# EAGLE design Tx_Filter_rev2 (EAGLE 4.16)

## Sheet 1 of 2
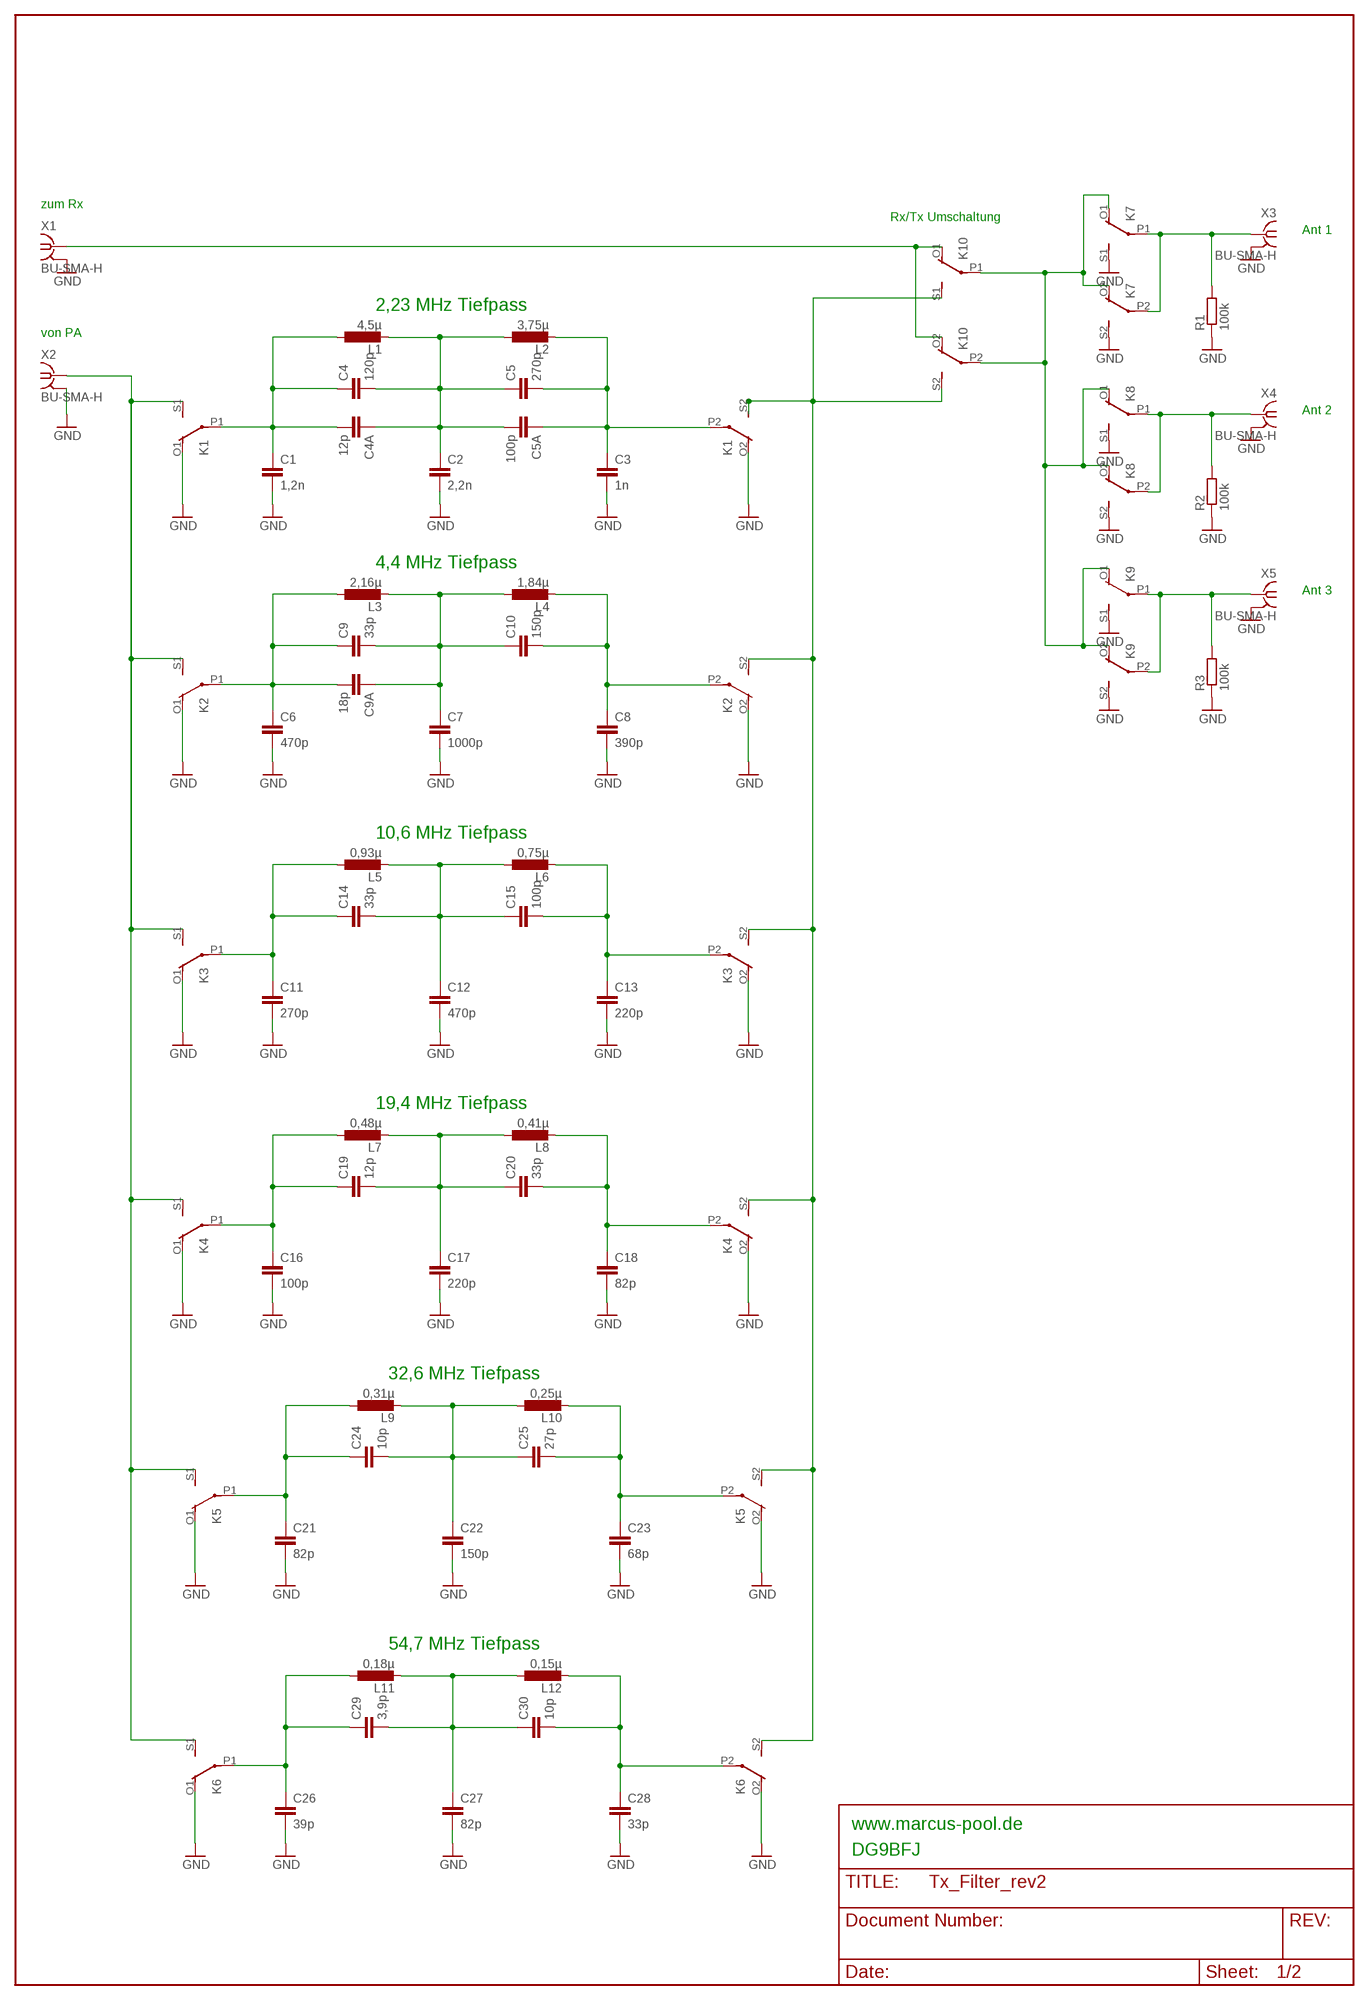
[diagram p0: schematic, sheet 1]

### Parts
C1  1,2n  C-EU050-035X075  [C050-035X075]
C2  2,2n  C-EU050-035X075  [C050-035X075]
C3  1n  C-EU050-035X075  [C050-035X075]
C4  120p  C-EU050-035X075  [C050-035X075]
C4A  12p  C-EU050-035X075  [C050-035X075]
C5  270p  C-EU050-035X075  [C050-035X075]
C5A  100p  C-EU050-035X075  [C050-035X075]
C6  470p  C-EU050-035X075  [C050-035X075]
C7  1000p  C-EU050-035X075  [C050-035X075]
C8  390p  C-EU050-035X075  [C050-035X075]
C9  33p  C-EU050-035X075  [C050-035X075]
C9A  18p  C-EU050-035X075  [C050-035X075]
C10  150p  C-EU050-035X075  [C050-035X075]
C11  270p  C-EU050-035X075  [C050-035X075]
C12  470p  C-EU050-035X075  [C050-035X075]
C13  220p  C-EU050-035X075  [C050-035X075]
C14  33p  C-EU050-035X075  [C050-035X075]
C15  100p  C-EU050-035X075  [C050-035X075]
C16  100p  C-EU050-035X075  [C050-035X075]
C17  220p  C-EU050-035X075  [C050-035X075]
C18  82p  C-EU050-035X075  [C050-035X075]
C19  12p  C-EU050-035X075  [C050-035X075]
C20  33p  C-EU050-035X075  [C050-035X075]
C21  82p  C-EU050-035X075  [C050-035X075]
C22  150p  C-EU050-035X075  [C050-035X075]
C23  68p  C-EU050-035X075  [C050-035X075]
C24  10p  C-EU050-035X075  [C050-035X075]
C25  27p  C-EU050-035X075  [C050-035X075]
C26  39p  C-EU050-035X075  [C050-035X075]
C27  82p  C-EU050-035X075  [C050-035X075]
C28  33p  C-EU050-035X075  [C050-035X075]
C29  3,9p  C-EU050-035X075  [C050-035X075]
C30  10p  C-EU050-035X075  [C050-035X075]
K1  G6H2-100  [G6H2-100]
K2  G6H2-100  [G6H2-100]
K3  G6H2-100  [G6H2-100]
K4  G6H2-100  [G6H2-100]
K5  G6H2-100  [G6H2-100]
K6  G6H2-100  [G6H2-100]
K7  G6H2-100  [G6H2-100]
K8  G6H2-100  [G6H2-100]
K9  G6H2-100  [G6H2-100]
K10  G6H2-100  [G6H2-100]
L1  4,5µ  L-EUTJ3-U1  [TJ3-U1]
L2  3,75µ  L-EUTJ3-U1  [TJ3-U1]
L3  2,16µ  L-EUTJ3-U1  [TJ3-U1]
L4  1,84µ  L-EUTJ3-U1  [TJ3-U1]
L5  0,93µ  L-EUTJ3-U1  [TJ3-U1]
L6  0,75µ  L-EUTJ3-U1  [TJ3-U1]
L7  0,48µ  L-EUTJ3-U1  [TJ3-U1]
L8  0,41µ  L-EUTJ3-U1  [TJ3-U1]
L9  0,31µ  L-EUTJ3-U1  [TJ3-U1]
L10  0,25µ  L-EUTJ3-U1  [TJ3-U1]
L11  0,18µ  L-EUTJ3-U1  [TJ3-U1]
L12  0,15µ  L-EUTJ3-U1  [TJ3-U1]
R1  100k  R-EU_M0805  [M0805]
R2  100k  R-EU_M0805  [M0805]
R3  100k  R-EU_M0805  [M0805]
X1  BU-SMA-H  [BU-SMA-H]
X2  BU-SMA-H  [BU-SMA-H]
X3  BU-SMA-H  [BU-SMA-H]
X4  BU-SMA-H  [BU-SMA-H]
X5  BU-SMA-H  [BU-SMA-H]

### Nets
GND: C1.2 C2.2 C3.2 C6.2 C7.2 C8.2 C11.2 C12.2 C13.2 C16.2 C17.2 C18.2 C21.2 C22.2 C23.2 C26.2 C27.2 C28.2 K1.O1(2:O) K1.O2(3:O) K2.O1(2:O) K2.O2(3:O) K3.O1(2:O) K3.O2(3:O) K4.O1(2:O) K4.O2(3:O) K5.O1(2:O) K5.O2(3:O) K6.O1(2:O) K6.O2(3:O) K7.S1(2:S) K7.S2(3:S) K8.S1(2:S) K8.S2(3:S) K9.S1(2:S) K9.S2(3:S) R1.1 R2.1 R3.1 X1.2(GND) X2.2(GND) X3.2(GND) X4.2(GND) X5.2(GND) ; also sheet 2
N$1: C1.1 C4.1 C4A.2 K1.P1(2:P) L1.1
N$2: C2.1 C4.2 C4A.1 C5.1 C5A.2 L1.2 L2.1
N$3: C6.1 C9.1 C9A.2 K2.P1(2:P) L3.1
N$4: C8.1 C10.2 K2.P2(3:P) L4.2
N$5: C3.1 C5.2 C5A.1 K1.P2(3:P) L2.2
N$6: C7.1 C9.2 C9A.1 C10.1 L3.2 L4.1
N$7: C11.1 C14.1 K3.P1(2:P) L5.1
N$8: C13.1 C15.2 K3.P2(3:P) L6.2
N$9: C12.1 C14.2 C15.1 L5.2 L6.1
N$10: C16.1 C19.1 K4.P1(2:P) L7.1
N$11: C18.1 C20.2 K4.P2(3:P) L8.2
N$12: C17.1 C19.2 C20.1 L7.2 L8.1
N$13: C21.1 C24.1 K5.P1(2:P) L9.1
N$14: C23.1 C25.2 K5.P2(3:P) L10.2
N$15: C22.1 C24.2 C25.1 L9.2 L10.1
N$16: C26.1 C29.1 K6.P1(2:P) L11.1
N$17: C28.1 C30.2 K6.P2(3:P) L12.2
N$18: C27.1 C29.2 C30.1 L11.2 L12.1
N$21: K7.P1(2:P) K7.P2(3:P) R1.2 X3.1
N$22: K7.O1(2:O) K7.O2(3:O) K8.O1(2:O) K8.O2(3:O) K9.O1(2:O) K9.O2(3:O) K10.P1(2:P) K10.P2(3:P)
N$24: K8.P1(2:P) K8.P2(3:P) R2.2 X4.1
N$25: K9.P1(2:P) K9.P2(3:P) R3.2 X5.1
RX: K10.O1(2:O) K10.O2(3:O) X1.1
TX_IN: K1.S1(2:S) K2.S1(2:S) K3.S1(2:S) K4.S1(2:S) K5.S1(2:S) K6.S1(2:S) X2.1
TX_OUT: K1.S2(3:S) K2.S2(3:S) K3.S2(3:S) K4.S2(3:S) K5.S2(3:S) K6.S2(3:S) K10.S1(2:S) K10.S2(3:S)

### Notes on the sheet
- zum Rx
- Rx/Tx Umschaltung
- Ant 1
- 2,23 MHz Tiefpass
- von PA
- Ant 2
- 4,4 MHz Tiefpass
- Ant 3
- 10,6 MHz Tiefpass
- 19,4 MHz Tiefpass
- 32,6 MHz Tiefpass
- 54,7 MHz Tiefpass
- www.marcus-pool.de
- DG9BFJ

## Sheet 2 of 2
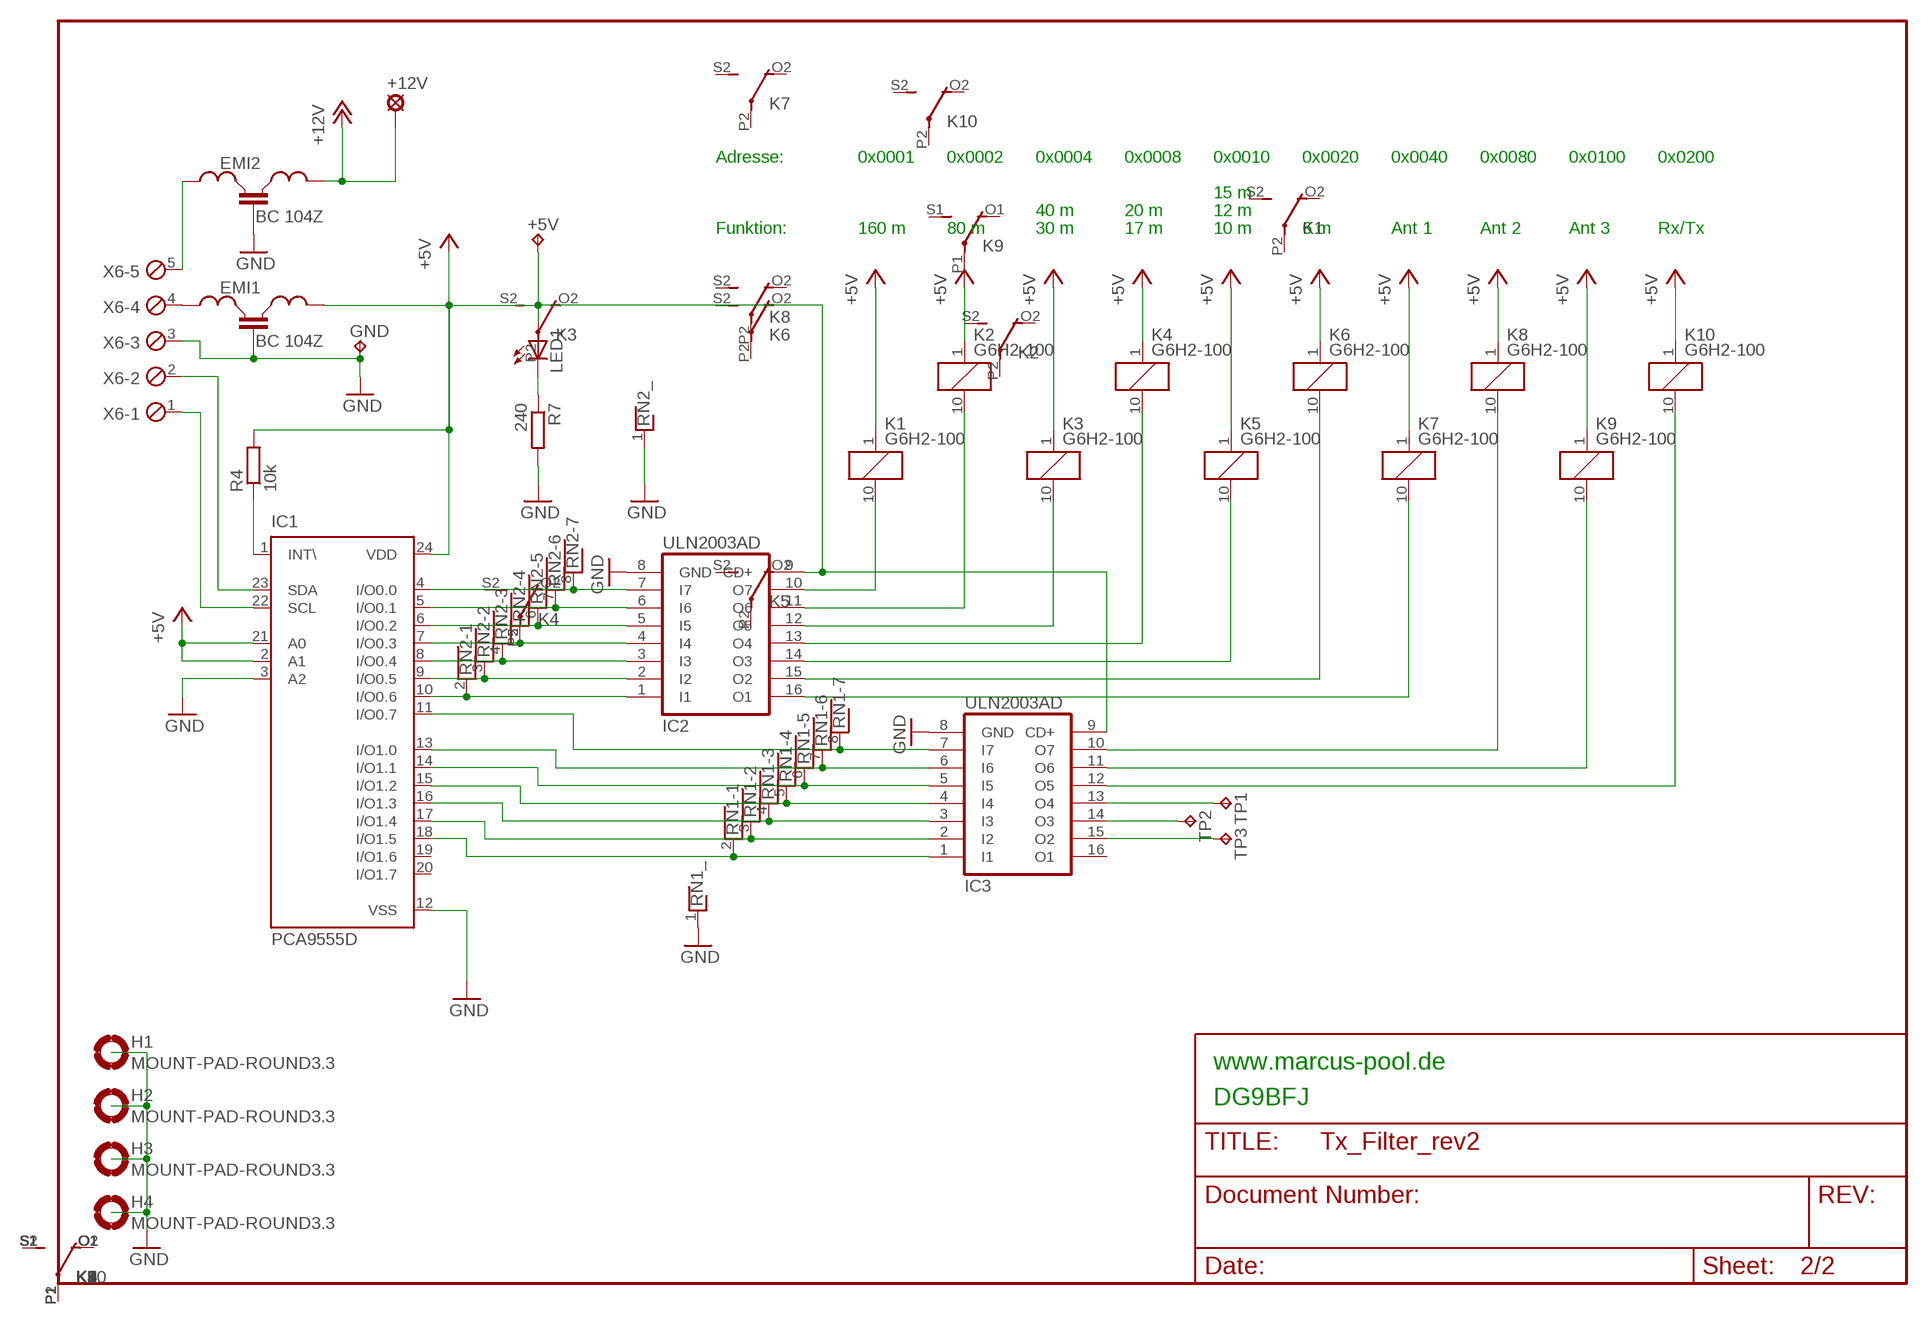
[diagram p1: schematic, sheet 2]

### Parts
+5V  TPB2,54  [B2,54]
+12V  LSP10  [LSP10]
EMI1  BC 104Z  DSS30655  [DSS30655]
EMI2  BC 104Z  DSS30655  [DSS30655]
GND  TPB2,54  [B2,54]
H1  MOUNT-PAD-ROUND3.3  [3,3-PAD]
H2  MOUNT-PAD-ROUND3.3  [3,3-PAD]
H3  MOUNT-PAD-ROUND3.3  [3,3-PAD]
H4  MOUNT-PAD-ROUND3.3  [3,3-PAD]
IC1  PCA9555D  [SO24]
IC2  ULN2003AD  [SO16]
IC3  ULN2003AD  [SO16]
LED1  LEDCHIP-LED0805  [CHIP-LED0805]
R4  10k  R-EU_M0805  [M0805]
R7  240  R-EU_M0805  [M0805]
RN1  RNX7  [RN-8]
RN2  RNX7  [RN-8]
TP1  TPB2,54  [B2,54]
TP2  TPB2,54  [B2,54]
TP3  TPB2,54  [B2,54]
X6  MPT5  [5POL254]

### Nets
+5V: +5V.PP(TP) EMI1.3 IC1.2(A1) IC1.21(A0) IC1.24(VDD) IC2.9(CD+) IC3.9(CD+) K1.1 K2.1 K3.1 K4.1 K5.1 K6.1 K7.1 K8.1 K9.1 K10.1 LED1.A R4.2
+12V: +12V.MP EMI2.3
GND: EMI1.2 EMI2.2 GND.PP(TP) H1.B3,3(MOUNT) H2.B3,3(MOUNT) H3.B3,3(MOUNT) H4.B3,3(MOUNT) IC1.3(A2) IC1.12(VSS) IC2.8(GND) IC3.8(GND) R7.2 RN1.1 RN2.1 X6.3 ; also sheet 1
N$19: IC1.10(I/O0.6) IC2.1(I1) RN2.2
N$20: IC2.10(O7) K1.10
N$23: IC2.11(O6) K2.10
N$26: IC2.12(O5) K3.10
N$27: IC2.13(O4) K4.10
N$28: IC2.14(O3) K5.10
N$29: IC2.15(O2) K6.10
N$30: IC2.16(O1) K7.10
N$31: IC3.10(O7) K8.10
N$32: IC1.11(I/O0.7) IC3.7(I7) RN1.8
N$33: IC1.13(I/O1.0) IC3.6(I6) RN1.7
N$34: IC1.9(I/O0.5) IC2.2(I2) RN2.3
N$35: IC1.14(I/O1.1) IC3.5(I5) RN1.6
N$36: IC1.15(I/O1.2) IC3.4(I4) RN1.5
N$37: IC1.16(I/O1.3) IC3.3(I3) RN1.4
N$38: IC1.17(I/O1.4) IC3.2(I2) RN1.3
N$39: IC1.8(I/O0.4) IC2.3(I3) RN2.4
N$40: IC1.7(I/O0.3) IC2.4(I4) RN2.5
N$41: IC1.6(I/O0.2) IC2.5(I5) RN2.6
N$42: IC1.5(I/O0.1) IC2.6(I6) RN2.7
N$43: IC1.4(I/O0.0) IC2.7(I7) RN2.8
N$44: IC1.18(I/O1.5) IC3.1(I1) RN1.2
N$45: IC3.11(O6) K9.10
N$46: IC3.12(O5) K10.10
N$47: IC1.1(INT\) R4.1
N$48: IC3.15(O2) TP3.PP(TP)
N$49: IC3.14(O3) TP2.PP(TP)
N$50: IC3.13(O4) TP1.PP(TP)
N$51: EMI1.1 X6.4
N$52: EMI2.1 X6.5
N$70: IC1.22(SCL) X6.1
N$71: IC1.23(SDA) X6.2
N$72: LED1.C R7.1
Unconnected: IC1.19(I/O1.6) IC1.20(I/O1.7) IC3.16(O1)

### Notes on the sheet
- Adresse: | 0x0001 | 0x0002 | 0x0004 | 0x0008 | 0x0010 | 0x0020 | 0x0040 | 0x0080 | 0x0100 | 0x0200
- 15 m
- 40 m | 20 m | 12 m
- Funktion: | 160 m | 80 m | 30 m | 17 m | 10 m | 6 m | Ant 1 | Ant 2 | Ant 3 | Rx/Tx
- www.marcus-pool.de
- DG9BFJ

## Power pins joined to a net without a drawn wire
GND: X1.3(GND) X1.4(GND) X1.5(GND) X2.3(GND) X2.4(GND) X2.5(GND) X3.3(GND) X3.4(GND) X3.5(GND) X4.3(GND) X4.4(GND) X4.5(GND) X5.3(GND) X5.4(GND) X5.5(GND)

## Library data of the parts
+5V GND TP1-TP3 = RSC_IB_LIB:TP
+12V = solpad:LSP10: SOLDER PAD
C1-C4 C4A C5 C5A C6-C9 C9A C10-C30 = rcl:C-EU: CAPACITOR, European symbol
EMI1 EMI2 = ds(s)30655:DSS30655
H1-H4 = holes:MOUNT-PAD-ROUND: MOUNTING PAD, round
IC1 = micro-philips:PCA9555: 16-bit I2C and SMBus I/O port with interrupt Source: PCA9555_5.pdf
IC2 IC3 = uln-udn:ULN2003A: DRIVER ARRAY
K1-K10 = relay:G6H2-100: RELAY 2 x switch, 0.5 A/125 V AC, 1 A/30 V DC, Omron
L1-L12 = rcl:L-EU: INDUCTOR, European symbol
LED1 = led:LED: LED
R1-R4 R7 = rcl:R-EU_: RESISTOR, European symbol
RN1 RN2 = resistor-net:RNX7: RESISTOR NETWORK
X1-X5 = RSC_IB_LIB:BU-SMA-H
X6 = con-phoenix-254:MPT5: PHOENIX CONNECTOR

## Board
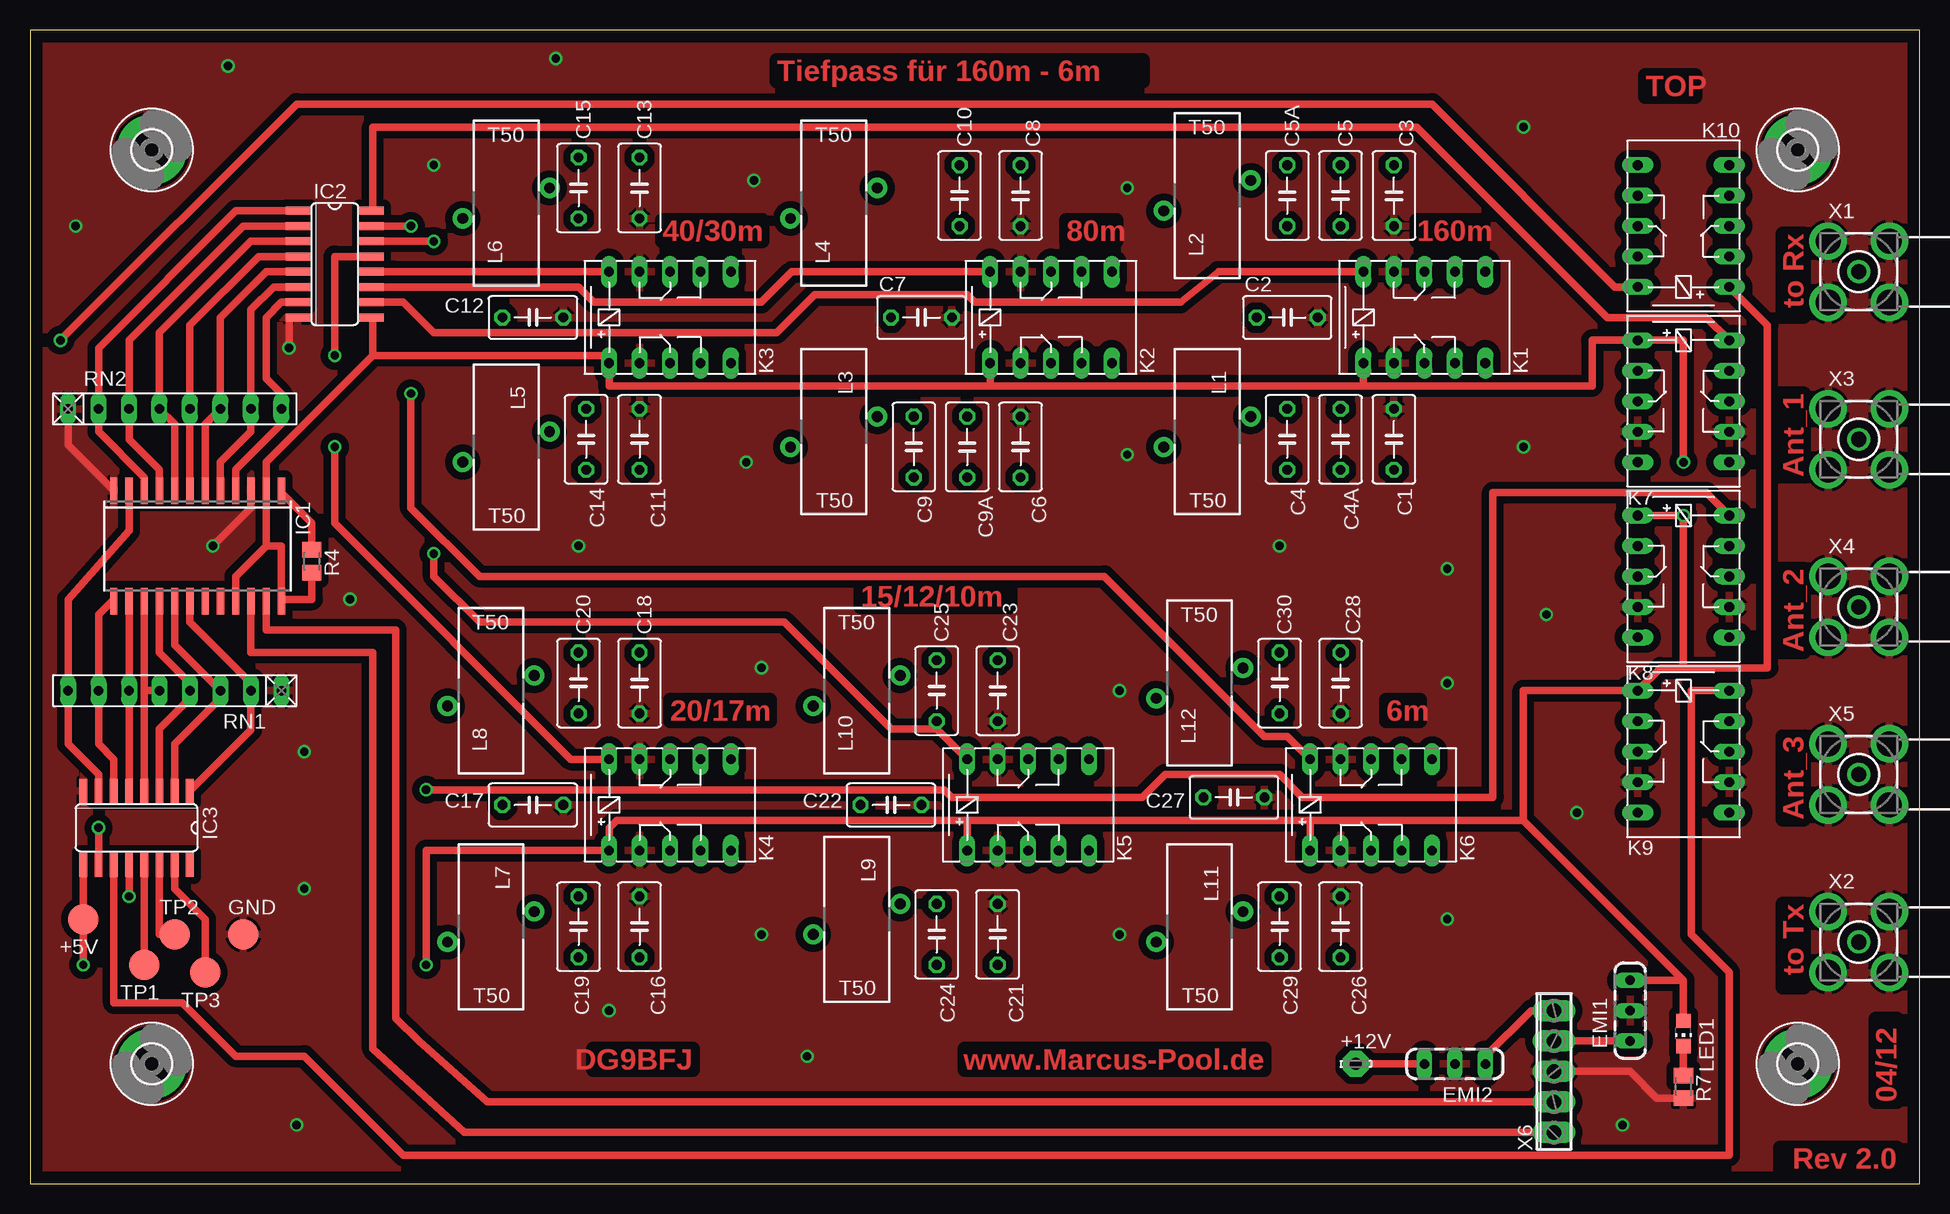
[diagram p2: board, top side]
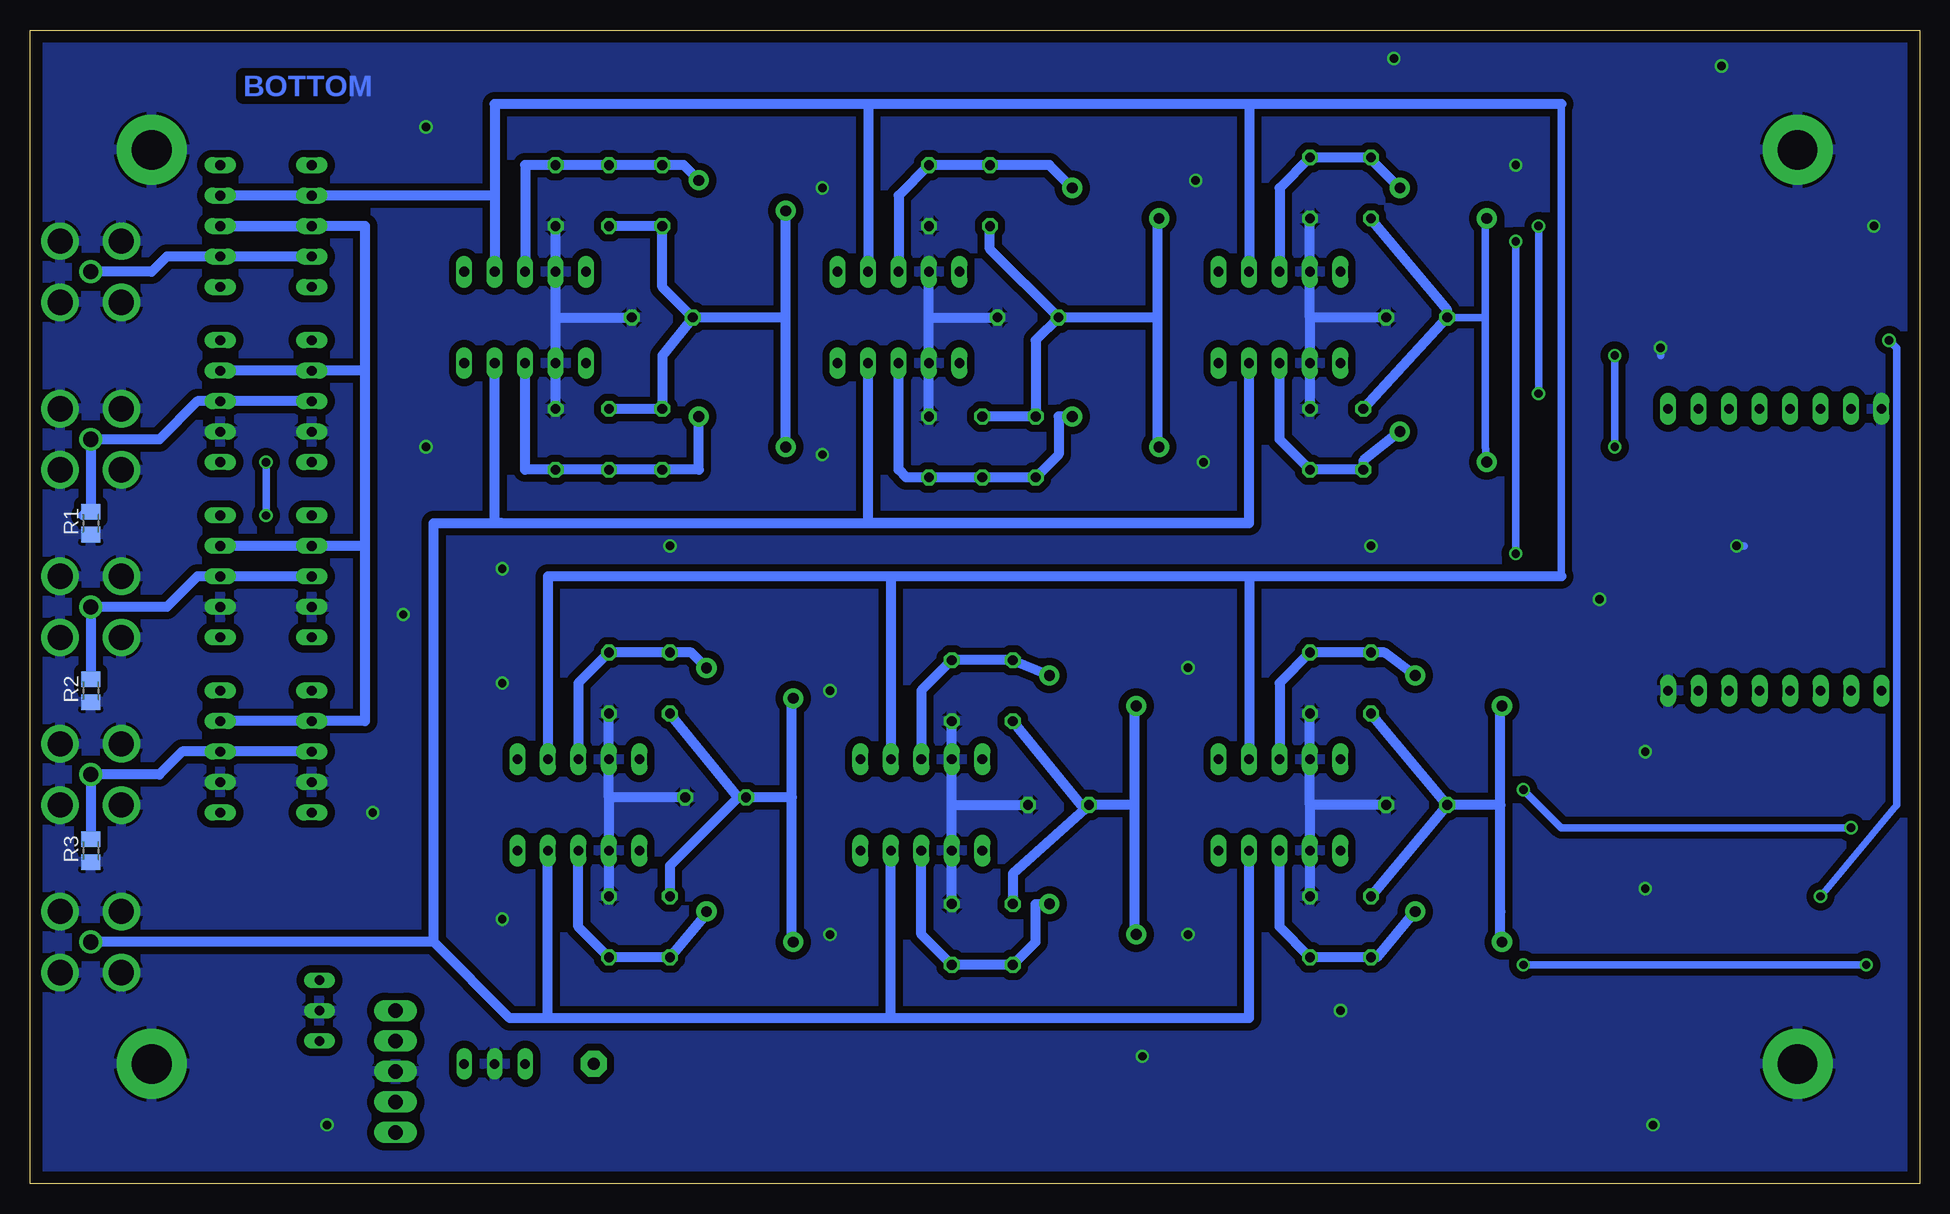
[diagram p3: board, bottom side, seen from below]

Size 157.46 x 96.19 mm. Coordinates in mm from the lower left corner, seen from the top.
Outline: 0,0 157.46,0 157.46,96.19 0,96.19 0,0
Copper layers (1*16): Top 0.035mm / dielectric 1.5mm / Bottom 0.035mm
Design rules "Bilex DRU": minimum track width 10mil, minimum drill 24mil, track to track 10mil, track to pad 10mil, pad to pad 10mil, via to via 10mil, smd to smd 10mil, copper to edge 40mil, drill to drill 8mil, minimum pad ring 10mil, minimum via ring 8mil, stop-mask expansion 4mil, vias tented up to drill 0mil, thermal gap 10mil

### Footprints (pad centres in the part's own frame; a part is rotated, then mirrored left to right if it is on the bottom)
B2,54 = smd 2.54 x 2.54: PP 0,0
LSP10 = drill 1.016 pad 2.159 octagon: MP 0,0
C050-035X075 = drill 0.813 octagon: 1 -2.54,0; 2 2.54,0
DSS30655 = drill 0.8 long: 1 -2.54,0; 2 0,0; 3 2.54,0
3,3-PAD = drill 3.3 pad 5.842 round: B3,3 0,0
SO24 = smd 0.6 x 2.2: 1 -6.985,-4.6; 2 -5.715,-4.6; 3 -4.445,-4.6; 4 -3.175,-4.6; 5 -1.905,-4.6; 6 -0.635,-4.6; 7 0.635,-4.6; 8 1.905,-4.6; 9 3.175,-4.6; 10 4.445,-4.6; 11 5.715,-4.6; 12 6.985,-4.6; 13 6.985,4.6; 14 5.715,4.6; 15 4.445,4.6; 16 3.175,4.6; 17 1.905,4.6; 18 0.635,4.6; 19 -0.635,4.6; 20 -1.905,4.6; 21 -3.175,4.6; 22 -4.445,4.6; 23 -5.715,4.6; 24 -6.985,4.6
SO16 = smd 0.66 x 2.032: 1 -4.445,-3.073; 2 -3.175,-3.073; 3 -1.905,-3.073; 4 -0.635,-3.073; 5 0.635,-3.073; 6 1.905,-3.073; 7 3.175,-3.073; 8 4.445,-3.073; 9 4.445,3.073; 10 3.175,3.073; 11 1.905,3.073; 12 0.635,3.073; 13 -0.635,3.073; 14 -1.905,3.073; 15 -3.175,3.073; 16 -4.445,3.073
G6H2-100 = drill 0.813 long: 1 -5.08,-3.81; 5 5.08,-3.81; 6 5.08,3.81; 10 -5.08,3.81; O1 -2.54,-3.81; O2 -2.54,3.81; P1 0,-3.81; P2 0,3.81; S1 2.54,-3.81; S2 2.54,3.81
TJ3-U1 = drill 0.9 pad 1.676 round: 1 -3.935,-1.27; 2 3.3,1.27
CHIP-LED0805 = smd 1.2 x 1.2: A 0,-1.05; C 0,1.05
M0805 = smd 1.3 x 1.6: 1 -0.95,0; 2 0.95,0
RN-8 = drill 0.813 long: 1 -8.89,0; 2 -6.35,0; 3 -3.81,0; 4 -1.27,0; 5 1.27,0; 6 3.81,0; 7 6.35,0; 8 8.89,0
BU-SMA-H = drill 1.27 round: 1 0,0 | drill 2.1 round: 2 -2.55,2.55; 3 2.55,2.55; 4 2.55,-2.55; 5 -2.55,-2.55
5POL254 = drill 1.2 long: 1 -5.08,0; 2 -2.54,0; 3 0,0; 4 2.54,0; 5 5.08,0

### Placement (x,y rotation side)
+5V  4.44,22.06 180 top
+12V  110.48,10 0 top
C1  113.66,62.06 90 top
C2  104.77,72.22 0 top
C3  113.66,82.38 270 top
C4  104.77,62.06 90 top
C4A  109.22,62.06 270 top
C5  109.22,82.38 90 top
C5A  104.77,82.38 270 top
C6  82.55,61.43 90 top
C7  74.29,72.22 0 top
C8  82.55,82.38 270 top
C9  73.66,61.43 90 top
C9A  78.1,61.43 270 top
C10  77.47,82.38 90 top
C11  50.79,62.06 90 top
C12  41.9,72.22 0 top
C13  50.79,83.02 270 top
C14  46.35,62.06 90 top
C15  45.71,83.02 90 top
C16  50.79,21.43 90 top
C17  41.9,31.59 0 top
C18  50.79,41.74 270 top
C19  45.71,21.43 90 top
C20  45.71,41.74 90 top
C21  80.64,20.79 90 top
C22  71.75,31.59 0 top
C23  80.64,41.11 270 top
C24  75.56,20.79 90 top
C25  75.56,41.11 90 top
C26  109.22,21.43 90 top
C27  100.33,32.22 0 top
C28  109.22,41.74 270 top
C29  104.14,21.43 90 top
C30  104.14,41.74 90 top
EMI1  133.34,14.44 90 top
EMI2  118.74,10 180 top
GND  17.78,20.79 0 top
H1  147.31,10 0 top
H2  10.15,10 0 top
H3  10.15,86.19 0 top
H4  147.31,86.19 0 top
IC1  13.96,53.18 180 top
IC2  25.39,76.67 270 top
IC3  8.88,29.68 180 top
K1  116.2,72.22 0 top
K2  85.09,72.22 0 top
K3  53.34,72.22 0 top
K4  53.34,31.59 0 top
K5  83.18,31.59 0 top
K6  111.76,31.59 0 top
K7  137.79,65.24 270 top
K8  137.79,50.63 270 top
K9  137.79,36.03 270 top
K10  137.79,79.84 90 top
L1  97.79,62.7 180 top
L2  98.42,82.38 0 top
L3  66.67,62.7 180 top
L4  67.31,81.75 0 top
L5  39.36,61.43 180 top
L6  40,81.75 0 top
L7  38.09,21.43 180 top
L8  38.73,41.11 0 top
L9  68.58,22.06 180 top
L10  69.21,41.11 0 top
L11  97.15,21.43 180 top
L12  97.79,41.74 0 top
LED1  137.79,12.54 180 top
R1  152.4,55.08 90 bottom
R2  152.4,41.11 90 bottom
R3  152.4,27.78 90 bottom
R4  23.49,51.91 270 top
R7  137.79,8.09 270 top
RN1  12.06,41.11 180 top
RN2  12.06,64.6 0 top
TP1  9.52,18.25 180 top
TP2  12.06,20.79 0 top
TP3  14.6,17.62 180 top
X1  152.4,76.03 0 top
X2  152.4,20.16 0 top
X3  152.4,62.06 0 top
X4  152.4,48.09 0 top
X5  152.4,34.12 0 top
X6  127,9.36 90 top

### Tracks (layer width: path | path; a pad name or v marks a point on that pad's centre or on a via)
+5V  (via drill 0.7)
  Top 0.61: IC1.21 17.14,50.63 19.68,53.18 | K10.1 144.78,71.59 144.78,43.02 | 144.78,43.02 137.79,43.02 v137.79,55.72 K8.1 | 144.78,43.02 135.88,43.02 K9.1 124.45,41.11 124.45,30.32 | 78.1,30.32 48.89,30.32 48.25,29.68 K4.1 33.02,27.78 v33.02,18.25 | 78.1,30.32 K5.1 | 78.1,30.32 106.68,30.32 | 106.68,30.32 K6.1 | 106.68,30.32 124.45,30.32 | 80.01,66.51 48.25,66.51 K3.1 48.25,69.05 28.57,69.05 | 80.01,66.51 K2.1 | 111.12,66.51 80.01,66.51 | 111.12,66.51 K1.1 | 111.12,66.51 130.17,66.51 130.17,70.32 K7.1 137.79,70.32 v137.79,60.16 | 124.45,30.32 137.79,16.98 | 137.79,16.98 LED1.A | 19.68,53.18 IC1.2 19.68,60.16 28.57,69.05 | 19.68,53.18 20.95,53.18 20.95,48.73 | 20.95,48.73 23.49,48.73 R4.2 | 20.95,48.73 IC1.24 | 137.79,16.98 EMI1.3 | IC2.9 28.57,72.22 28.57,69.05 | +5V.PP IC3.9 +5V.PP | v4.44,18.25 +5V.PP
  Bottom 0.61: v137.79,55.72 v137.79,60.16 | v4.44,18.25 v33.02,18.25
+12V
  Top 0.61: +12V.MP EMI2.3
GND  (via drill 0.7)
  Top 0.61: 18.41,57.62 IC1.3 18.41,56.35 v15.23,53.18 | IC1.12 6.98,57.62 | IC1.12 6.98,58.26 | R7.2 135.56,7.14 133.34,9.36 X6.3 | IC1.12 3.17,61.59 RN2.1 | IC2.8 21.59,72.22 v21.59,69.68
  Bottom 0.61: 14.6,53.18 v15.23,53.18 | v21.59,69.68 21.59,69.05
  Bottom 0.813: C1.2 K1.O1 113.66,72.22 | 113.66,72.22 K1.O2 C3.2 | 113.66,72.22 C2.2 | C12.2 50.79,72.22 | 50.79,72.22 K3.O1 C11.2 | 50.79,72.22 K3.O2 C13.2 | 82.55,72.22 C7.2 | 82.55,72.22 K2.O1 C6.2 | 82.55,72.22 K2.O2 | C16.2 K4.O1 50.79,31.59 | 50.79,31.59 K4.O2 C18.2 | C17.2 50.79,31.59 | 80.64,31.59 C22.2 | 80.64,31.59 K5.O1 C21.2 | 80.64,31.59 K5.O2 C23.2 | 109.22,32.22 K6.O1 C26.2 | 109.22,32.22 K6.O2 C28.2 | C27.2 109.22,32.22
  other vias: 126.36,47.46 26.67,48.73 22.86,36.03 22.86,24.6 60.95,20.79 60.95,43.02 48.25,14.44 64.77,10.63 90.8,20.79 90.8,41.11 118.11,51.27 118.11,41.74 118.11,22.06 128.9,30.95 132.71,4.92 124.45,61.43 124.45,88.1 91.44,83.02 91.44,60.8 59.68,60.16 60.32,83.65 33.65,84.92 45.71,53.18 16.51,93.18 3.81,79.84 43.81,93.81 22.22,4.92 104.14,53.18
  pour Bottom (isolate 0.61): 0.63,95.72 0.63,0.47 156.84,0.47 156.84,95.72
  pour Top (isolate 0.61): 0.63,95.72 0.63,0.47 156.84,0.47 156.84,95.72
N$1
  Bottom 0.813: K1.P1 116.2,59.52 C1.1 C4A.2 C4.1 101.72,59.52 L1.1
N$2
  Bottom 0.813: C4A.1 C4.2 104.77,69.05 C2.1 | C5.1 C5A.2 104.77,74.77 C2.1 | L1.2 94.48,72.22 | 94.48,72.22 L2.1 | 94.48,72.22 C2.1
N$3
  Bottom 0.813: K2.P1 85.09,59.52 84.45,58.89 C6.1 C9A.2 C9.1 71.75,60.8 71.75,63.97 L3.1
N$4
  Bottom 0.813: L4.2 72.51,84.92 C10.2 C8.1 85.09,82.38 K2.P2
N$5
  Bottom 0.813: K1.P2 116.2,84.92 C3.1 C5.2 C5A.1 102.99,84.92 L2.2
N$6
  Bottom 0.813: C9A.1 C9.2 73.66,70.32 C7.1 | C7.1 77.47,77.94 C10.1 | L3.2 63.49,61.43 63.49,72.22 | L4.1 63.49,80.35 63.49,72.22 | 63.49,72.22 C7.1
N$7
  Bottom 0.813: L5.1 46.35,60.29 C14.1 C11.1 53.34,62.06 K3.P1
N$8
  Bottom 0.813: K3.P2 53.34,83.02 C13.1 C15.2 45.84,85.56 L6.2
N$9
  Bottom 0.61: L6.1 36.19,80.48 36.19,72.22 | L5.2 36.19,61.55 36.19,72.22 | 36.19,72.22 C12.1
  Bottom 0.813: C14.2 C12.1 39.36,72.86 C15.1
N$10
  Bottom 0.813: L7.1 45.2,18.89 C19.1 C16.1 53.34,21.43 K4.P1
N$11
  Bottom 0.813: L8.2 44.57,44.29 C20.2 C18.1 53.34,41.74 K4.P2
N$12
  Bottom 0.813: L8.1 34.92,39.72 34.92,31.59 | 34.92,31.59 34.92,22.7 34.92,20.91 L7.2 | 34.92,31.59 C17.1 | C17.1 C20.1 | C17.1 C19.2
N$13
  Bottom 0.813: K5.P1 83.18,20.79 C21.1 C24.1 73.66,20.16 73.66,23.33 L9.1
N$14
  Bottom 0.813: L10.2 75.69,43.65 C25.2 C23.1 83.18,41.11 K5.P2
N$15
  Bottom 0.813: C22.1 75.56,25.87 C24.2 | C25.1 69.84,31.59 C22.1 | L9.2 65.4,20.79 65.4,31.59 | L10.1 65.4,39.08 65.4,31.59 | 65.4,31.59 C22.1
N$16
  Bottom 0.813: L11.1 100.96,22.7 C29.1 C26.1 111.76,21.43 K6.P1
N$17
  Bottom 0.813: L12.2 102.36,44.29 C30.2 C28.1 111.76,41.74 K6.P2
N$18
  Bottom 0.813: L11.2 93.98,20.16 93.98,32.22 | L12.1 93.98,40.35 93.98,32.22 | 93.98,32.22 C27.1 98.42,32.22 | 98.42,32.22 C30.1 | 98.42,32.22 104.14,26.51 C29.2
N$19
  Top 0.61: IC1.10 9.52,58.89 5.71,62.7 RN2.2 5.71,69.68 17.14,81.11 IC2.1
N$20
  Top 0.61: K1.10 99.06,76.03 95.88,73.49 78.73,73.49 78.1,74.13 65.4,74.13 62.22,70.95 33.65,70.95 31.11,73.49 IC2.10
N$21
  Bottom 0.813: 142.24,65.24 K7.P2 | 142.24,65.24 143.5,65.24 146.68,62.06 X3.1 R1.2 153.03,55.72 | K7.P1 142.24,65.24
N$22
  Bottom 0.813: K10.P2 K10.P1 129.53,79.84 129.53,67.78 | 129.53,53.18 129.53,38.57 K9.O1 K9.O2 | 129.53,53.18 129.53,67.78 | K7.O2 K7.O1 129.53,67.78 | 129.53,53.18 K8.O1 K8.O2
N$23
  Top 0.61: K2.10 63.49,76.03 60.95,73.49 46.98,73.49 45.71,74.77 31.11,74.77 | 31.11,74.77 28.57,74.77 | IC2.11 31.11,74.77
N$24
  Bottom 0.813: K8.P1 K8.P2 143.5,50.63 146.05,48.09 X4.1 R2.2
N$25
  Bottom 0.813: K9.P1 K9.P2 144.78,36.03 146.68,34.12 X5.1 R3.2
N$26
  Top 0.61: 30.48,76.03 28.57,76.03 | 30.48,76.03 K3.10 | IC2.12 30.48,76.03
N$27  (via drill 0.7)
  Top 0.61: K4.10 45.08,35.4 25.39,55.08 v25.39,61.43 | v25.39,69.05 25.39,77.3 IC2.13 28.57,77.3
  Bottom 0.61: v25.39,61.43 v25.39,69.05
N$28  (via drill 0.7)
  Top 0.61: K5.10 75.56,37.94 71.75,37.94 62.86,46.83 37.46,46.83 33.65,50.63 v33.65,52.54 | v33.65,78.57 IC2.14
  Bottom 0.61: v33.65,52.54 v33.65,78.57
N$29  (via drill 0.7)
  Top 0.61: K6.10 104.77,37.3 102.87,37.3 89.53,50.63 37.46,50.63 31.75,56.35 v31.75,65.88 | v31.75,79.84 IC2.15
  Bottom 0.61: v31.75,65.88 v31.75,79.84
N$30
  Top 0.61: K7.10 139.69,72.22 131.44,72.22 115.56,88.1 28.57,88.1 28.57,81.22 IC2.16
N$31  (via drill 0.7)
  Top 0.61: K8.10 139.69,57.62 121.92,57.62 121.92,32.22 106.04,32.22 104.14,34.12 94.61,34.12 92.7,32.22 76.83,32.22 76.2,32.86 v33.02,32.86 | 5.71,26.51 IC3.10 v5.71,29.68
  Bottom 0.61: v33.02,32.86 29.84,29.68 v5.71,29.68
N$32
  Top 0.61: IC1.11 8.25,54.45 3.17,48.73 RN1.8 3.17,36.66 5.71,34.12 IC3.7
N$33
  Top 0.61: IC1.13 6.98,48.73 5.71,47.46 RN1.7 5.71,36.66 6.98,35.4 IC3.6
N$34
  Top 0.61: IC1.9 10.79,59.52 8.25,62.06 RN2.3 8.25,70.32 17.78,79.84 IC2.2
N$35
  Top 0.61: 8.25,48.73 IC1.14 RN1.6 IC3.5
N$36
  Top 0.61: 9.52,41.11 IC1.15 | IC3.4 9.52,41.11 | 9.52,41.11 RN1.5
N$37
  Top 0.406: IC1.16 10.79,48.73
  Top 0.61: IC1.16 10.79,44.29 13.33,41.74 RN1.4 13.33,40.48 10.79,37.94 IC3.3
N$38
  Top 0.406: IC1.17 12.06,48.73
  Top 0.61: IC1.17 12.06,44.92 RN1.3 15.87,40.48 12.06,36.66 IC3.2
N$39
  Top 0.61: IC1.8 12.06,63.34 RN2.4 10.79,70.95 18.41,78.57 IC2.3
N$40
  Top 0.61: IC1.7 RN2.5 13.33,71.59 19.05,77.3 IC2.4
N$41
  Top 0.61: 14.6,57.62 IC1.6 14.6,63.34 RN2.6 15.87,72.22 19.68,76.03 IC2.5
N$42
  Top 0.61: IC1.5 15.87,60.16 18.41,62.7 RN2.7 18.41,72.86 20.32,74.77 IC2.6
N$43
  Top 0.61: IC1.4 17.14,59.52 20.95,63.34 RN2.8 20.95,65.88 19.68,67.14 19.68,72.22 20.95,73.49 IC2.7
N$44
  Top 0.61: IC1.18 13.33,46.83 18.41,41.74 RN1.2 18.41,37.83 IC3.1
N$45
  Top 0.61: K9.10 138.43,41.11 138.43,20.79 141.6,17.62 141.6,2.38 31.11,2.38 22.86,10.63 17.14,10.63 12.69,15.08 6.98,15.08 IC3.11
N$46  (via drill 0.7)
  Top 0.61: K10.10 132.08,74.77 116.84,90 22.22,90 v2.54,70.32 | v8.25,23.96 IC3.12
  Bottom 0.61: v8.25,23.96 1.9,31.59 1.9,69.68 v2.54,70.32
N$47
  Top 0.61: IC1.1 20.95,57.62 23.49,55.08 R4.1
N$48
  Top 0.61: IC3.15 12.06,24.6 14.6,22.06 TP3.PP
N$49
  Top 0.61: IC3.14 10.79,20.79 TP2.PP
N$50
  Top 0.61: TP1.PP IC3.13
N$51
  Top 0.61: X6.4 EMI1.1
N$52
  Top 0.61: X6.5 125.09,14.44 121.28,10.63 EMI2.1
N$70
  Top 0.61: 18.41,48.73 IC1.22 18.41,44.29 28.57,44.29 28.57,11.27 36.19,4.28 X6.1
N$71
  Top 0.61: X6.2 38.09,6.82 32.38,11.9 30.48,13.81 30.48,46.19 19.68,46.19 IC1.23 19.68,48.73
N$72
  Top 0.61: R7.1 LED1.C
RX
  Bottom 0.813: K10.O1 K10.O2 146.05,77.3 147.31,76.03 X1.1
TX_IN
  Bottom 0.813: 85.72,13.81 55.88,13.81 K4.S1 | 85.72,13.81 K5.S1 | 114.3,13.81 K6.S1 | 85.72,13.81 114.3,13.81 | K2.S1 87.62,55.08 86.99,55.08 | 55.88,55.08 86.99,55.08 | 55.88,55.08 K3.S1 | K1.S1 118.74,55.08 118.11,55.08 | 118.11,55.08 86.99,55.08 | 123.82,55.08 118.11,55.08 | 123.82,55.08 55.88,55.08 | 123.82,20.16 123.82,55.08 | 114.3,13.81 117.47,13.81 123.82,20.16 | 123.82,20.16 X2.1
TX_OUT
  Bottom 0.61: 29.84,50.63 29.84,90
  Bottom 0.813: 55.88,90 K3.S2 | 55.88,90 86.99,90 | 86.99,90 87.62,90 K2.S2 | 118.74,90 K1.S2 | 86.99,90 118.74,90 | K6.S2 114.3,50.63 85.72,50.63 | 85.72,50.63 K5.S2 | 55.88,50.63 85.72,50.63 | 55.88,50.63 K4.S2 | 29.84,50.63 55.88,50.63 | 29.84,90 55.88,90 | K10.S1 K10.S2 118.74,82.38 118.74,90

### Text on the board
Top: Tiefpass für 160m - 6m | TOP | 40/30m | 80m | 160m | to Rx | Ant_1 | Ant_2 | 15/12/10m | 20/17m | 6m | Ant_3 | to Tx | DG9BFJ | www.Marcus-Pool.de | 04/12 | Rev 2.0
Bottom: BOTTOM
